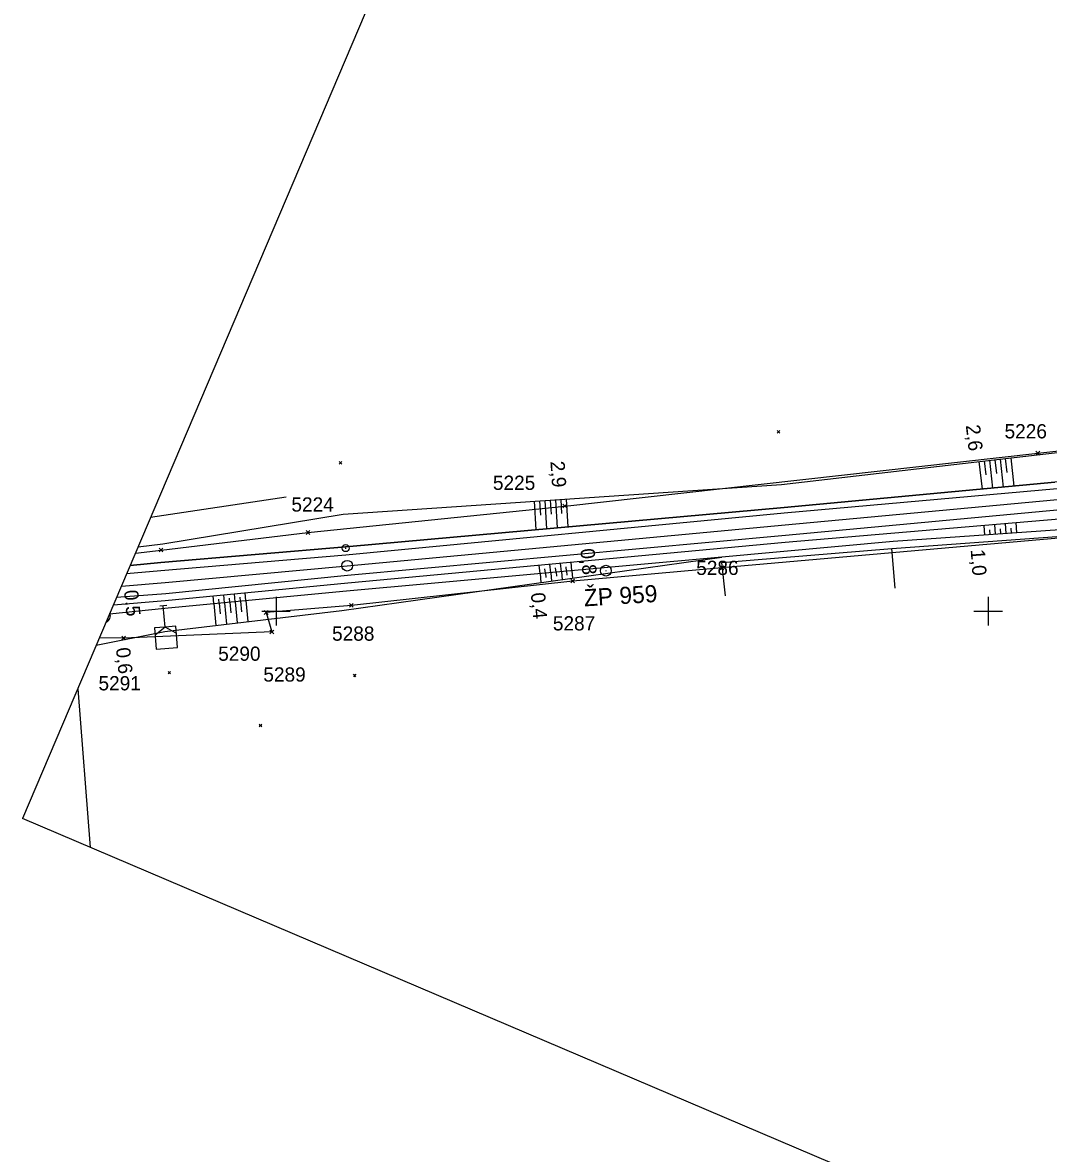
# Model space of a CAD drawing. Extents: x -805636 to -804553, y -1165340 to -1164656.
# Drawn here: x -805635.6 to -805491.5, y -1164976.1 to -1164817.4 of the extents above; entities that cross this region are included whole.
import ezdxf

# ---------------------------------------------------------------- set-up
doc = ezdxf.new("R2010")
doc.units = 0
for name, color, linetype in [('0381KM061-064P - Vrstva 1', 7, 'Continuous'), ('0381KM061-064P - Vrstva 17', 7, 'Continuous'), ('0381KM061-064P - Vrstva 4', 7, 'Continuous'), ('0381KM061-064P - Vrstva 48', 7, 'Continuous'), ('0381KM061-064P - Vrstva 49', 7, 'Continuous'), ('0381KM061-064P - Vrstva 7', 7, 'Continuous'), ('0381KM061-064P - Vrstva 8', 7, 'Continuous'), ('formát', 7, 'Continuous'), ('krizky_1000 - Vrstva 1', 7, 'Continuous'), ('szdc - hran DP', 7, 'Continuous'), ('szdc - szdc_cislo', 7, 'Continuous'), ('szdc - szdc_krizek', 7, 'Continuous'), ('vyt_sit - stávající', 7, 'Continuous')]:
    doc.layers.add(name, color=color, linetype=linetype)

msp = doc.modelspace()

# ---------------------------------------------------------------- linework, layer by layer
at = {"layer": '0381KM061-064P - Vrstva 1'}
msp.add_lwpolyline([(-805621.7, -1164896.48), (-805615.58, -1164895.98), (-805590.01, -1164893.62), (-805528.48, -1164887.9), (-805486.76, -1164883.98), (-805461.3, -1164882.03), (-805437.69, -1164881.51), (-805413.27, -1164883.66)], dxfattribs=at)
at = {"layer": '0381KM061-064P - Vrstva 17'}
for p, q in [((-805598.57, -1164884.01), (-805617.61, -1164886.87)), ((-805513.07, -1164896.77), (-805513.54, -1164891.19))]:
    msp.add_line(p, q, dxfattribs=at)
msp.add_lwpolyline([(-805536.86, -1164897.86), (-805537.37, -1164893.17), (-805513.54, -1164891.19), (-805489.69, -1164889.49), (-805460.65, -1164887.61), (-805460.29, -1164888.19), (-805437.32, -1164886.99), (-805436.25, -1164891.59)], dxfattribs=at)
at = {"layer": '0381KM061-064P - Vrstva 4'}
for p, q in [((-805528.63, -1164885.47), (-805490.63, -1164881.9)), ((-805490.28, -1164882.82), (-805528.62, -1164886.23)), ((-805589.69, -1164890.91), (-805528.63, -1164885.47)), ((-805528.62, -1164886.23), (-805590.21, -1164892.16)), ((-805616.18, -1164893.18), (-805589.69, -1164890.91)), ((-805620.48, -1164893.61), (-805616.18, -1164893.18)), ((-805590.21, -1164892.16), (-805616.16, -1164894.34)), ((-805616.16, -1164894.34), (-805620.98, -1164894.78))]:
    msp.add_line(p, q, dxfattribs=at)
for points in [[(-805622.83, -1164899.13), (-805615.58, -1164898.49), (-805589.92, -1164896.02), (-805528.49, -1164890.34), (-805490.03, -1164887.06), (-805461.18, -1164884.75), (-805437.91, -1164883.87), (-805413.61, -1164886.43), (-805397.33, -1164889.69), (-805391.36, -1164890.97), (-805383.82, -1164892.41)], [(-805383.82, -1164892.41), (-805391.14, -1164890.05), (-805413.4, -1164885.24), (-805437.69, -1164883.08), (-805461.24, -1164883.62), (-805489.81, -1164885.79), (-805528.46, -1164889.37), (-805589.94, -1164895), (-805615.48, -1164897.55), (-805622.38, -1164898.08)]]:
    msp.add_lwpolyline(points, dxfattribs=at)
at = {"layer": '0381KM061-064P - Vrstva 48'}
for p, q in [((-805501.3, -1164879), (-805500.85, -1164882.86)), ((-805500.56, -1164878.91), (-805500.33, -1164880.85)), ((-805499.81, -1164878.83), (-805499.36, -1164882.72)), ((-805499.07, -1164878.74), (-805498.84, -1164880.7)), ((-805498.32, -1164878.66), (-805497.87, -1164882.58)), ((-805497.58, -1164878.57), (-805497.35, -1164880.54)), ((-805496.83, -1164878.48), (-805496.37, -1164882.44)), ((-805563.76, -1164884.57), (-805563.49, -1164888.58)), ((-805563.01, -1164884.52), (-805562.88, -1164886.51)), ((-805562.27, -1164884.47), (-805562, -1164888.44)), ((-805561.52, -1164884.42), (-805561.38, -1164886.4)), ((-805560.77, -1164884.36), (-805560.5, -1164888.31)), ((-805560.02, -1164884.31), (-805559.89, -1164886.28)), ((-805559.27, -1164884.26), (-805559.01, -1164888.18)), ((-805500.46, -1164889.32), (-805500.56, -1164887.96)), ((-805499.71, -1164889.27), (-805499.76, -1164888.58)), ((-805498.96, -1164889.21), (-805499.06, -1164887.83)), ((-805498.21, -1164889.16), (-805498.26, -1164888.46)), ((-805497.46, -1164889.11), (-805497.57, -1164887.7)), ((-805496.72, -1164889.05), (-805496.77, -1164888.34)), ((-805495.97, -1164889), (-805496.07, -1164887.57)), ((-805562.92, -1164894.73), (-805563.03, -1164893.53)), ((-805561.43, -1164894.6), (-805561.53, -1164893.4)), ((-805559.93, -1164894.46), (-805560.04, -1164893.26)), ((-805558.44, -1164894.33), (-805558.55, -1164893.12)), ((-805562.92, -1164894.73), (-805562.81, -1164895.99)), ((-805562.17, -1164894.66), (-805562.23, -1164894.06)), ((-805562.17, -1164894.66), (-805562.12, -1164895.27)), ((-805561.43, -1164894.6), (-805561.32, -1164895.78)), ((-805560.68, -1164894.53), (-805560.73, -1164893.93)), ((-805560.68, -1164894.53), (-805560.63, -1164895.1)), ((-805559.93, -1164894.46), (-805559.83, -1164895.57)), ((-805559.19, -1164894.4), (-805559.24, -1164893.79)), ((-805559.19, -1164894.4), (-805559.14, -1164894.93)), ((-805558.44, -1164894.33), (-805558.35, -1164895.36)), ((-805608.72, -1164898.95), (-805608.83, -1164897.84)), ((-805607.97, -1164898.88), (-805608.03, -1164898.32)), ((-805607.23, -1164898.81), (-805607.33, -1164897.7)), ((-805606.48, -1164898.74), (-805606.53, -1164898.18)), ((-805605.73, -1164898.67), (-805605.84, -1164897.55)), ((-805604.99, -1164898.59), (-805605.04, -1164898.04)), ((-805604.24, -1164898.52), (-805604.35, -1164897.41)), ((-805608.72, -1164898.95), (-805608.43, -1164902)), ((-805607.97, -1164898.88), (-805607.83, -1164900.4)), ((-805607.23, -1164898.81), (-805606.94, -1164901.82)), ((-805606.48, -1164898.74), (-805606.34, -1164900.24)), ((-805605.73, -1164898.67), (-805605.45, -1164901.65)), ((-805604.99, -1164898.59), (-805604.84, -1164900.08)), ((-805604.24, -1164898.52), (-805603.96, -1164901.47))]:
    msp.add_line(p, q, dxfattribs=at)
at = {"layer": '0381KM061-064P - Vrstva 49'}
for p, q in [((-805529.26, -1164875), (-805529.61, -1164874.64)), ((-805529.26, -1164874.64), (-805529.61, -1164875)), ((-805590.78, -1164879.37), (-805591.13, -1164879.01)), ((-805590.78, -1164879.01), (-805591.13, -1164879.37)), ((-805614.8, -1164908.81), (-805615.15, -1164908.45)), ((-805614.8, -1164908.45), (-805615.15, -1164908.81)), ((-805588.77, -1164909.21), (-805589.13, -1164908.86)), ((-805588.77, -1164908.86), (-805589.13, -1164909.21)), ((-805602, -1164916.26), (-805602.35, -1164915.9)), ((-805602, -1164915.9), (-805602.35, -1164916.26))]:
    msp.add_line(p, q, dxfattribs=at)
for points in [[(-805619.35, -1164890.95), (-805615.91, -1164890.53), (-805590.56, -1164886.39), (-805529.03, -1164882.21), (-805489.9, -1164877.68), (-805461.98, -1164874.39), (-805438.96, -1164873.66), (-805412.14, -1164878.2), (-805389.29, -1164884.48), (-805375.6, -1164889.14)], [(-805379.56, -1164889.14), (-805389.79, -1164885.89), (-805412.78, -1164881.05), (-805437.82, -1164878.81), (-805461.56, -1164879.34), (-805490.63, -1164881.9), (-805528.63, -1164885.47), (-805589.69, -1164890.91), (-805616.18, -1164893.18), (-805620.48, -1164893.61)], [(-805622.83, -1164899.13), (-805615.58, -1164898.49), (-805589.92, -1164896.02), (-805528.49, -1164890.34), (-805490.03, -1164887.06), (-805461.18, -1164884.75), (-805437.91, -1164883.87), (-805413.61, -1164886.43), (-805397.33, -1164889.69), (-805394.79, -1164892.28)], [(-805394.79, -1164892.28), (-805397.93, -1164890.9), (-805413.8, -1164887.77), (-805437.96, -1164885.62), (-805460.38, -1164886.37), (-805489.93, -1164888.57), (-805513.35, -1164890.24), (-805537.4, -1164892.44), (-805590.64, -1164897.22), (-805615.62, -1164899.61), (-805623.38, -1164900.43)], [(-805625.24, -1164904.79), (-805615.6, -1164902.86), (-805590.78, -1164899.89), (-805537.4, -1164892.44)]]:
    msp.add_lwpolyline(points, dxfattribs=at)
at = {"layer": '0381KM061-064P - Vrstva 7'}
for p, q in [((-805590.27, -1164891.15), (-805590.17, -1164891.14)), ((-805615.33, -1164899.2), (-805616.33, -1164899.28)), ((-805615.58, -1164902.23), (-805615.83, -1164899.24))]:
    msp.add_line(p, q, dxfattribs=at)
for points in [[(-805615.58, -1164902.23), (-805617.08, -1164902.35), (-805616.83, -1164905.34), (-805613.84, -1164905.1), (-805614.09, -1164902.11), (-805615.58, -1164902.23)], [(-805614, -1164903.1), (-805615.58, -1164902.23), (-805616.99, -1164903.35)]]:
    msp.add_lwpolyline(points, dxfattribs=at)
for centre, radius in [((-805590.22, -1164891.15), 0.5), ((-805590, -1164893.62), 0.75)]:
    msp.add_circle(centre, radius, dxfattribs=at)
at = {"layer": '0381KM061-064P - Vrstva 8'}
for p, q in [((-805623.32, -1164900.29), (-805623.86, -1164901.55)), ((-805627.84, -1164910.91), (-805626.08, -1164933.16))]:
    msp.add_line(p, q, dxfattribs=at)
msp.add_arc((-805624.26, -1164900.63), 1, 293.9534, 19.9498, dxfattribs=at)
at = {"layer": 'formát'}
for p in [(-805519.31, -1164655.82), (-805055.88, -1165175.77)]:
    msp.add_line(p, (-805635.59, -1164929.12), dxfattribs=at)
at = {"layer": 'krizky_1000 - Vrstva 1'}
for points in [[(-805600, -1164898), (-805600, -1164902)], [(-805500, -1164898), (-805500, -1164902)], [(-805602, -1164900), (-805598, -1164900)], [(-805502, -1164900), (-805498, -1164900)]]:
    msp.add_lwpolyline(points, dxfattribs=at)
at = {"layer": 'szdc - hran DP'}
for p, q in [((-805493.02, -1164877.83), (-805461.06, -1164874.13)), ((-805559.43, -1164885.25), (-805493.02, -1164877.83)), ((-805595.52, -1164888.96), (-805559.43, -1164885.25)), ((-805472.98, -1164888.24), (-805537.37, -1164893.92)), ((-805616.15, -1164891.42), (-805595.52, -1164888.96)), ((-805619.74, -1164891.88), (-805616.15, -1164891.42)), ((-805537.37, -1164893.92), (-805558.32, -1164895.77)), ((-805558.32, -1164895.77), (-805589.42, -1164899.19)), ((-805589.42, -1164899.19), (-805601.38, -1164900.18)), ((-805601.38, -1164900.18), (-805600.58, -1164902.92)), ((-805600.58, -1164902.92), (-805621.39, -1164903.78)), ((-805621.39, -1164903.78), (-805624.8, -1164903.76))]:
    msp.add_line(p, q, dxfattribs=at)
at = {"layer": 'szdc - szdc_krizek'}
for p, q in [((-805492.75, -1164878.09), (-805493.29, -1164877.56)), ((-805493.29, -1164878.09), (-805492.75, -1164877.56)), ((-805559.16, -1164885.51), (-805559.7, -1164884.98)), ((-805559.7, -1164885.51), (-805559.16, -1164884.98)), ((-805595.25, -1164889.23), (-805595.78, -1164888.7)), ((-805595.78, -1164889.23), (-805595.25, -1164888.7)), ((-805615.89, -1164891.69), (-805616.42, -1164891.16)), ((-805616.42, -1164891.69), (-805615.89, -1164891.16)), ((-805537.1, -1164894.19), (-805537.64, -1164893.66)), ((-805537.64, -1164894.19), (-805537.1, -1164893.66)), ((-805558.06, -1164896.03), (-805558.59, -1164895.51)), ((-805558.59, -1164896.03), (-805558.06, -1164895.51)), ((-805601.12, -1164900.45), (-805601.65, -1164899.92)), ((-805601.65, -1164900.45), (-805601.12, -1164899.92)), ((-805589.16, -1164899.45), (-805589.69, -1164898.92)), ((-805589.69, -1164899.45), (-805589.16, -1164898.92)), ((-805600.32, -1164903.18), (-805600.85, -1164902.65)), ((-805600.85, -1164903.18), (-805600.32, -1164902.65)), ((-805621.12, -1164904.05), (-805621.66, -1164903.52)), ((-805621.66, -1164904.05), (-805621.12, -1164903.52))]:
    msp.add_line(p, q, dxfattribs=at)
at = {"layer": 'vyt_sit - stávající'}
msp.add_line((-805553.71, -1164894.29), (-805553.63, -1164894.35), dxfattribs=at)
msp.add_circle((-805553.67, -1164894.32), 0.756, dxfattribs=at)

# ---------------------------------------------------------------- texts
at = {"layer": '0381KM061-064P - Vrstva 48'}
for s, rotation, p in [('2,6', 276.6062, (-805503.14, -1164873.92)), ('2,9', 273.8809, (-805561.47, -1164878.99)), ('0,8', 275.1319, (-805557.27, -1164891.28)), ('1,0', 274.074, (-805502.45, -1164891.38)), ('0,5', 276.0149, (-805621.37, -1164897.12)), ('0,4', 275.1319, (-805564.22, -1164897.47)), ('0,6', 276.0149, (-805622.49, -1164905.2))]:
    msp.add_text(s, height=2, rotation=rotation, dxfattribs=at).set_placement(p)
at = {"layer": 'szdc - szdc_cislo'}
for s, p in [('5226', (-805497.69, -1164875.75)), ('5225', (-805569.54, -1164882.98)), ('5224', (-805597.84, -1164886.03)), ('5286', (-805540.99, -1164894.92)), ('5287', (-805561.12, -1164902.71)), ('5288', (-805592.13, -1164904.15)), ('5290', (-805608.12, -1164906.97)), ('5289', (-805601.78, -1164909.89)), ('5291', (-805624.93, -1164911.12))]:
    msp.add_text(s, height=2, dxfattribs=at).set_placement(p)
at = {"layer": 'vyt_sit - stávající'}
msp.add_text('ŽP 959', height=2.4, rotation=3.5611, dxfattribs=at).set_placement((-805556.7, -1164899.34))

doc.saveas('drawing.dxf')
